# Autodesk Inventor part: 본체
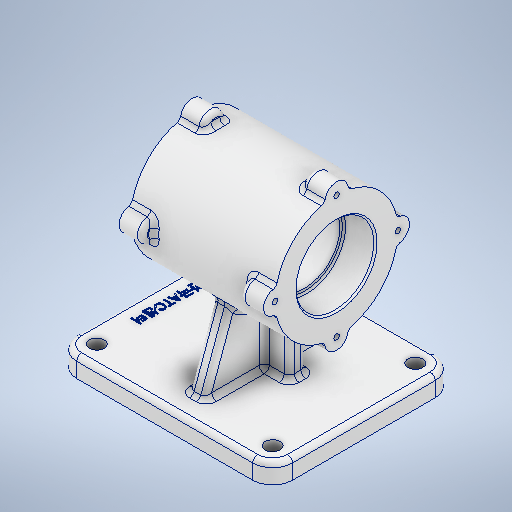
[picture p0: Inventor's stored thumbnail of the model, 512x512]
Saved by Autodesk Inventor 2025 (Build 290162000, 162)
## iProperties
Created: 2024-08
Part Number: 본체
Material: 알루미늄 6061
Document SubType Name: Modeling
Designer: 학생
Density: 2.7 g/cm^3
Appearance: 알루미늄 - 평지
Mass: 1215.39 g
Surface Area: 796.909 cm^2
Volume: 450.146 cm^3
Author: 학생
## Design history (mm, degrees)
sketch "스케치3"
  geometry: L1 (70, -55)-(70, 55); L2 (70, 55)-(-60, 55); L3 (-60, 55)-(-60, -55); L4 (-60, -55)-(70, -55); L5 (70, 0)-(140, 0); L6 (0, 0)-(70, 0)
  constraints: 12 end point, 2 horizontal, 2 horizontal alignment, 2 vertical alignment, 1 midpoint, 1 perpendicular, 1 vertical
  dimensions: "d6" = 110 distance of L2.end L3.end; "d10" = 70 distance of L5.start L6.start; "d11" = 130 distance between parallel lines of L1 L3
extrude "돌출1" new body sketch "스케치3" distance "d12" = 12; taper "d13" = 0 deg
sketch "스케치4"
  geometry: L1 (20, 5)-(-20, 5); L2 (-20, 5)-(-20, -5); L3 (-20, -5)-(20, -5); L4 (20, -5)-(20, 5); L5 (20, 5)-(-20, -5); L6 (-20, 5)-(20, -5); L7 (-5, 41)-(5, 41); L8 (5, 41)-(5, -41); L9 (5, -41)-(-5, -41); L10 (-5, -41)-(-5, 41); L11 (-5, 41)-(5, -41); L12 (5, 41)-(-5, -41); L13 (60, 55)-(-70, 55) reference; L14 (-70, -55)-(60, -55) reference; 6 further points
  constraints: 24 end point, 5 midpoint, 4 parallel, 2 horizontal, 2 perpendicular
  dimensions: "d14" = 10 distance of L1.end L2.end; "d15" = 10 distance of L8.end L9.end (= d14); "d16" = 40 distance of L1.start L1.end; "d17" = 82 distance of L7.end L8.end; "d18" = 14 distance from line of L13 point (0, 41) (derived); "d19" = 14 distance between parallel lines of L14 L9 (derived)
extrude "돌출2" join sketch "스케치4" distance "d20" = 60; taper "d21" = 0 deg
sketch "스케치5"
  geometry: L1 (0, 0)-(0, 82); L2 (-211.195, 82)-(211.195, 82); L3 (43.5, 45)-(-43.5, 45); L4 (-43.5, 45)-(-43.5, 119); L5 (-43.5, 119)-(43.5, 119); L6 (43.5, 119)-(43.5, 45); L7 (43.5, 45)-(-43.5, 119); L8 (-43.5, 45)-(43.5, 119); L9 (-43.5, 82)-(43.5, 82); 1 further point
  constraints: 18 end point, 4 midpoint, 2 horizontal, 2 parallel, 1 coincident, 1 perpendicular, 1 vertical
  dimensions: "d22" = 82 distance of L1.end L1.start; "d24" = 74 distance between parallel lines of L3 L5; "d27" = 87 distance of L4.end L5.end
revolve "회전1" sketch "스케치5" stored, may be unused: angle "d28" = 90 deg
feature "면 기울기1" dims angle "d29" = 20 deg
fillet "모깎기1" dims "d30" = 12
sketch "스케치6"
  geometry: L1 (-37, 0)-(37, 0); L2 (0, 37)-(0, -37); C1 r 7 at (0, 37); C2 r 7 at (-37, 0); C3 r 7 at (0, -37); C4 r 7 at (37, 0); A1 r 37 centre (0, 0) between (0, 37) and (-37, 0) reference; 3 further points
  constraints: 4 centre point, 4 end point, 4 midpoint, 4 point on circle, 3 equal radius, 1 horizontal, 1 vertical
  dimensions: "d31" = 14 diameter of C1
extrude "돌출3" join sketch "스케치6" distance "d32" = 14; taper "d33" = 0 deg
fillet "모깎기2" dims "d34" = 3
fillet "모깎기3" dims "d35" = 3
sketch "스케치7"
  geometry: L1 (-43.5, 91.104)-(-43.5, 117.863) reference; L2 (-43.5, 91.104)-(-32.5, 91.104) reference; L3 (-43.5, 91.104)-(-43.5, 117.863) reference; L4 (-32.5, 117.863)-(-43.5, 117.863) reference; L5 (-26.5, 118.912)-(-26.5, 118.913) reference; L6 (-43.5, 117.863)-(-32.5, 117.862) reference; L7 (-43.5, 117.863)-(-43.5, 91.104) reference; L8 (-32.5, 91.104)-(-43.5, 91.104) reference; L9 (-26.5, 79.457)-(-26.5, 84.543) reference; L10 (-43.5, 72.896)-(-32.5, 72.896) reference; L11 (-43.5, 72.896)-(-43.5, 46.138) reference; L12 (-32.5, 46.138)-(-43.5, 46.138) reference; L13 (-26.5, 45.088)-(-26.5, 45.088) reference; L14 (-43.5, 46.138)-(-32.5, 46.138) reference; L15 (-43.5, 46.138)-(-43.5, 72.896) reference; L16 (-32.5, 72.896)-(-43.5, 72.896) reference; L17 (-26.5, 84.543)-(-26.5, 79.457) reference; L18 (43.5, 72.896)-(32.5, 72.896) reference; L19 (43.5, 46.138)-(43.5, 72.896) reference; L20 (32.5, 46.138)-(43.5, 46.138) reference; L21 (26.5, 45.088)-(26.5, 45.088) reference; L22 (43.5, 46.138)-(32.5, 46.138) reference; L23 (43.5, 72.896)-(43.5, 46.138) reference; L24 (32.5, 72.896)-(43.5, 72.896) reference; L25 (26.5, 84.543)-(26.5, 79.457) reference; L26 (43.5, 91.104)-(32.5, 91.104) reference; L27 (43.5, 117.863)-(43.5, 91.104) reference; L28 (32.5, 117.862)-(43.5, 117.863) reference; L29 (26.5, 118.912)-(26.5, 118.912) reference; L30 (43.5, 117.863)-(32.5, 117.862) reference; L31 (43.5, 91.104)-(43.5, 117.863) reference; L32 (32.5, 91.104)-(43.5, 91.104) reference; L33 (26.5, 79.457)-(26.5, 84.543) reference; L34 (-5, 55.036)-(5, 55.036) reference; L35 (-5, 45.339)-(-5, 55.036) reference; L36 (-20, 45.339)-(-5, 45.339) reference; L37 (-20, 45.339)-(-20, 45.339) reference; L38 (-5, 45.339)-(-20, 45.339) reference; L39 (-5, 55.036)-(-5, 45.339) reference; L40 (-5, 55.036)-(5, 55.036) reference; L41 (5, 45.339)-(5, 55.036) reference; L42 (20, 45.339)-(5, 45.339) reference; L43 (20, 45.339)-(20, 45.339) reference; L44 (5, 45.339)-(20, 45.339) reference; L45 (5, 55.036)-(5, 45.339) reference; L46 (-43.5, 88.889)-(-43.5, 75.111) reference; L47 (-43.5, 82)-(43.5, 82); L48 (43.5, 88.889)-(43.5, 75.111) reference; L49 (-24.5, 58.5)-(-43.5, 58.5); L50 (-43.5, 58.5)-(-43.5, 82); L51 (-43.5, 82)-(-24.5, 82); L52 (-24.5, 82)-(-24.5, 58.5); L53 (-24.5, 58.5)-(-43.5, 82); L54 (-43.5, 58.5)-(-24.5, 82); L55 (43.5, 58.5)-(24.5, 58.5); L56 (24.5, 58.5)-(24.5, 82); L57 (24.5, 82)-(43.5, 82); L58 (43.5, 82)-(43.5, 58.5); L59 (43.5, 58.5)-(24.5, 82); L60 (24.5, 58.5)-(43.5, 82); L61 (24.5, 61)-(-24.5, 61); L62 (-24.5, 61)-(-24.5, 82); L63 (-24.5, 82)-(24.5, 82); L64 (24.5, 82)-(24.5, 61)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; 9 further points
  constraints: 38 end point, 8 midpoint, 6 parallel, 3 collinear, 3 horizontal, 3 perpendicular, 16 other
  dimensions: "d36" = 19 distance of L47.start L51.end; "d37" = 19 distance of L47.end L56.end (= d36); "d38" = 23.5 distance of L47.start L49.end; "d39" = 23.5 distance of L55.end L56.end (= d38); "d40" = 21 distance of L61.end L62.end
revolve "회전2" sketch "스케치7" stored, may be unused: angle "d41" = 90 deg
fillet "모깎기4" dims "d42" = 1
feature "결합1"
  node "솔리드2"
chamfer "모따기1" distance "d43" = 1; stored, may be unused: second distance "d44" = 2, angle "d45" = 45 deg
chamfer "모따기2" distance "d46" = 1; stored, may be unused: second distance "d47" = 2, angle "d48" = 45 deg
sketch "스케치8"
  geometry: C1 r 24.5 at (-37, 0) reference; A1 r 7 centre (-37, 37) between (-30.111, 38.239) and (-43.889, 38.239) reference; A2 r 7 centre (-74, 0) between (-75.239, 6.889) and (-75.239, -6.889) reference; A3 r 7 centre (-37, -37) between (-43.889, -38.239) and (-30.111, -38.239) reference; A4 r 7 centre (0, 0) between (1.239, -6.889) and (1.239, 6.889) reference; 5 further points
  constraints: 4 coincident, 2 horizontal alignment
hole "구멍1" sketch "스케치8" at (-37, 37), (-74, 0), (-37, -37), (0, 0) diameter "d49" = 3.242; stored, may be unused: countersink angle "d53" = 90 deg, drill point angle "d55" = 120 deg; dims "d50" = 8, "d51" = 4, "d52" = 2, "d54" = 10
fillet "모깎기5" dims "d60" = 3
fillet "모깎기6" dims "d61" = 3
sketch "스케치9"
  geometry: L1 (60, -43)-(60, 43) reference; A1 r 12 centre (-58, 43) between (-58, 55) and (-70, 43) reference; A2 r 12 centre (-58, -43) between (-70, -43) and (-58, -55) reference; A3 r 12 centre (48, -43) between (48, -55) and (60, -43) reference; 5 further points
  constraints: 3 coincident, 1 horizontal alignment, 1 vertical alignment
  dimensions: "d69" = 12 distance from line of L1 point (48, 43) (derived); "d70" = 86 distance of point (48, -43) point (48, 43) (derived)
hole "구멍2" sketch "스케치9" at (-58, 43), (-58, -43), (48, -43), (48, 43) diameter "d62" = 9; stored, may be unused: countersink angle "d66" = 90 deg, drill point angle "d68" = 0 deg; dims "d63" = 8, "d64" = 4, "d65" = 2, "d67" = 10
sketch "스케치10"
  geometry: 2 further points
  constraints: 1 horizontal alignment, 1 other
  dimensions: "d71" = 58 distance of point (0, 0) point (-58, 0)
feature "엠보싱1" sketch "스케치10" dims "d6" = 110, "d10" = 70, "d11" = 130, "d72" = 0.5, "d73" = 0
fillet "모깎기7" dims "d74" = 3
feature "Ձ耀Ճ耀Յ耀Շ耀Չ耀Ջ耀Ս耀Տ耀" dims "d6" = 110, "d10" = 70, "d11" = 130, "d12" = 12, "d13" = 0, "d14" = 10, "d15" = 10 (= d14), "d16" = 40, "d17" = 82, "d18" = 14 (derived), "d19" = 14 (derived), "d20" = 60, "d21" = 0, "d22" = 82, "d24" = 74, "d27" = 87, "d28" = 90 deg, "d29" = 20 deg, "d30" = 12, "d31" = 14, "d32" = 14, "d33" = 0, "d34" = 3, "d35" = 3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
node "솔리드1"
mirror "미러1"
mirror "미러2"
node "투영된 루프1"
feature "A9D066F2-1C7D-4E18-AEED-F7BC21143FA4" dims "d62" = 9, "d63" = 8, "d64" = 4, "d65" = 2, "d66" = 90 deg, "d67" = 10, "d68" = 0
